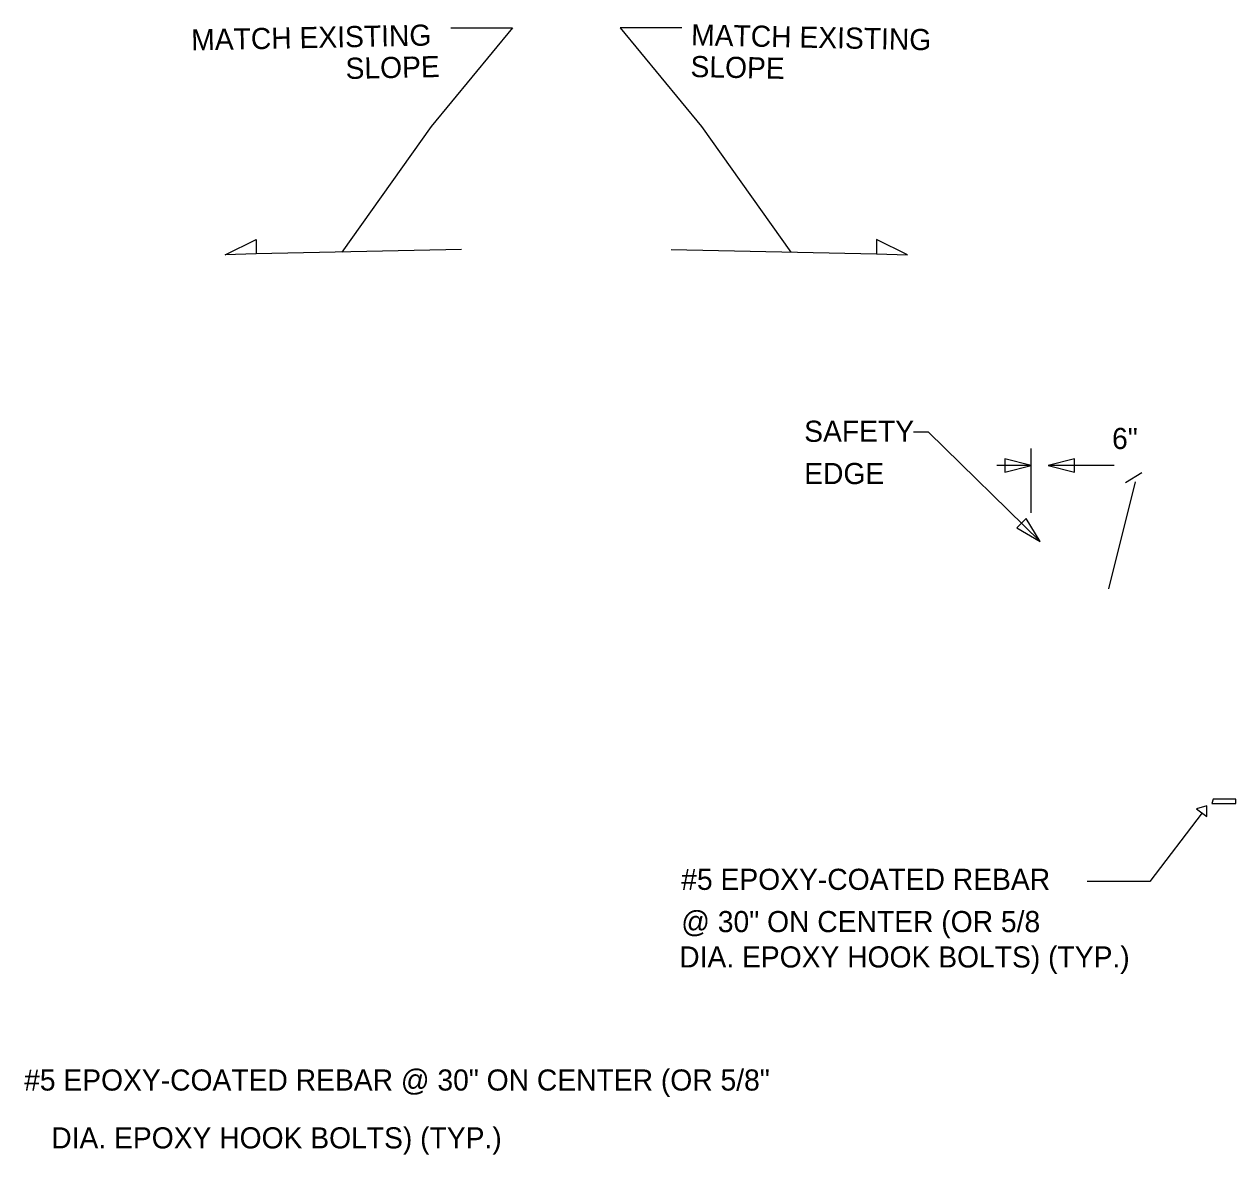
# Model space of a CAD drawing. Extents: x 227 to 993, y -530 to -180.
# Drawn here: x 226.77 to 270.08, y -244.34 to -203.93 of the extents above; entities that cross this region are included whole.
import ezdxf

# ---------------------------------------------------------------- set-up
doc = ezdxf.new("R2010")
doc.units = 0
for name, color, linetype in [('Default', 7, 'Continuous'), ('Level 11', 7, 'Continuous'), ('Level 40', 7, 'Continuous'), ('Level 59', 7, 'Continuous')]:
    doc.layers.add(name, color=color, linetype=linetype)

msp = doc.modelspace()

# ---------------------------------------------------------------- linework, layer by layer
at = {"layer": 'Default'}
for p, q in [((244.221, -204.056), (241.318, -207.581)), ((242.025, -204.056), (244.221, -204.056)), ((250.272, -204.056), (248.076, -204.056)), ((248.076, -204.056), (250.979, -207.581)), ((241.318, -207.581), (238.126, -212.074)), ((250.979, -207.581), (254.171, -212.074)), ((242.402, -211.985), (235.066, -212.137)), ((249.895, -211.985), (257.231, -212.137)), ((268.873, -232.122), (267.006, -234.572)), ((267.006, -234.572), (264.768, -234.572))]:
    msp.add_line(p, q, dxfattribs=at)
for points in [[(270.075, -231.782), (270.075, -231.624), (269.271, -231.624), (269.225, -231.782)], [(269.04, -231.862), (268.67, -231.975), (269.04, -232.245)]]:
    msp.add_lwpolyline(points, close=True, dxfattribs=at)
at = {"layer": 'Level 11'}
msp.add_line((266.719, -219.965), (266.132, -220.318), dxfattribs=at)
at = {"layer": 'Level 40'}
for points in [[(233.956, -212.171), (235.066, -211.619), (235.066, -212.137)], [(258.341, -212.171), (257.231, -211.619), (257.231, -212.137)]]:
    msp.add_lwpolyline(points, close=True, dxfattribs=at)
at = {"layer": 'Level 59'}
for p, q in [((259.087, -218.507), (258.56, -218.507)), ((263.087, -222.423), (259.087, -218.507)), ((262.761, -221.39), (262.761, -219.094)), ((262.761, -219.7), (261.535, -219.7)), ((265.731, -219.7), (263.366, -219.7)), ((265.543, -224.106), (266.49, -220.288))]:
    msp.add_line(p, q, dxfattribs=at)
for points in [[(261.819, -219.936), (262.761, -219.7), (261.819, -219.465)], [(264.308, -219.465), (263.366, -219.7), (264.308, -219.936)], [(262.25, -221.929), (263.087, -222.423), (262.581, -221.594)]]:
    msp.add_lwpolyline(points, close=True, dxfattribs=at)

# ---------------------------------------------------------------- texts
at = {"layer": 'Default'}
for s, height, rotation, p in [('MATCH EXISTING', 0.75504, 1.1927, (232.749, -204.869)), ('MATCH EXISTING', 0.75504, 358.8073, (250.603, -204.683)), ('SLOPE', 0.755, 1.1927, (238.264, -205.887)), ('SLOPE', 0.755, 358.8073, (250.58, -205.815))]:
    msp.add_text(s, height=height, rotation=rotation, dxfattribs=at).set_placement(p)
for s, p in [('#5 EPOXY-COATED REBAR', (250.256, -234.871)), ('@ 30" ON CENTER (OR 5/8', (250.256, -236.381)), ('DIA. EPOXY HOOK BOLTS) (TYP.)', (250.183, -237.645)), ('#5 EPOXY-COATED REBAR @ 30" ON CENTER (OR 5/8"', (226.768, -242.044)), ('DIA. EPOXY HOOK BOLTS) (TYP.)', (227.738, -244.112))]:
    msp.add_text(s, height=0.75504, dxfattribs=at).set_placement(p)
at = {"layer": 'Level 59'}
for s, p in [('SAFETY', (254.65, -218.856)), ('6"', (265.654, -219.113)), ('EDGE', (254.65, -220.366))]:
    msp.add_text(s, height=0.755, dxfattribs=at).set_placement(p)

doc.saveas('drawing.dxf')
